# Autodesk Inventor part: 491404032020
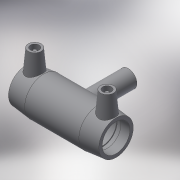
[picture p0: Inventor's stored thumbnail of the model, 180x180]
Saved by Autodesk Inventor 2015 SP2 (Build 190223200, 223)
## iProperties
Created: 2017-06
Part Number: 491404032020
Material: Generic
Description: PLASSON REDUCING TEE 32x20x32
Document SubType Name: Modeling
Designer: KIM
Mass: 57.3761 g
Surface Area: 241.06 cm^2
Volume: 57.3761 cm^3
Density: 1 g/cm^3
Appearance: Default
Author: KIM
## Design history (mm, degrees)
derived "491404.ipt"
feature "Solid1::491404.ipt"
tag "TaggingFeature1"
body "Solid1"
other parameters: "d0" = 104, "d1" = 32, "d2" = 44, "d3" = 39, "d4" = 20.8, "d5" = 39.6, "d6" = 30.4, "d7" = 32, "d8" = 168 deg, "d10" = 15.6, "d11" = 5.2, "d13" = 104, "d14" = 17.6296, "d17" = 28.8, "d18" = 32, "d19" = 3.52592, "d20" = 168 deg, "d22" = 40.92, "d23" = 44, "d25" = 135 deg, "d26" = 72.8, "d29" = 43, "d30" = 15, "d31" = 41.6, "d34" = 5 deg, "d35" = 15, "d39" = 5 deg, "d41" = 4, "d42" = 14, "d43" = 0, "d45" = 4, "d46" = 6, "d47" = 0, "d48" = -66, "d51" = 0, "d52" = 16, "d54" = 0, "d55" = 39.6, "d56" = 44, "d57" = 36.4, "d58" = 135 deg, "d59" = 39, "d60" = 39, "d61" = 135 deg, "d62" = 66, "d72" = 47.32, "d73" = 23.66, "d74" = -66, "d75" = 21, "d77" = 0, "d78" = 16, "d80" = 0, "d82" = 44, "d83" = 0, "d84" = 3, "d85" = 0, "d86" = 13, "d87" = 40.1016, "d88" = 5.2, "d89" = 3, "d90" = 0, "d_" = 32, "L_" = 104, "L_1" = 39, "D_" = 44, "A_" = 43, "d_2" = 12, "H_" = 66
